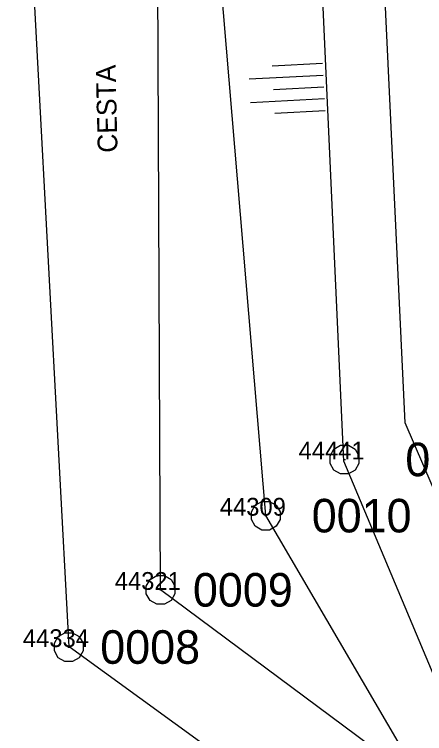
# Model space of a CAD drawing. Extents: x -598521 to -597689, y -1074676 to -1074150.
# Drawn here: x -598496.3 to -598485.91, y -1074215.4 to -1074197.17 of the extents above; entities that cross this region are included whole.
import ezdxf

# ---------------------------------------------------------------- set-up
doc = ezdxf.new("R2010")
doc.units = 0
for name, color, linetype in [('Vrstva 1', 7, 'Continuous'), ('Vrstva 10', 7, 'Continuous'), ('Vrstva 2', 7, 'Continuous'), ('Vrstva 3', 7, 'Continuous'), ('Vrstva 5', 7, 'Continuous')]:
    doc.layers.add(name, color=color, linetype=linetype)

msp = doc.modelspace()

# ---------------------------------------------------------------- linework, layer by layer
at = {"layer": 'Vrstva 1'}
for p, q in [((-598487.964, -1074208.45), (-598487.914, -1074208.45)), ((-598489.96, -1074209.873), (-598489.91, -1074209.873)), ((-598492.622, -1074211.753), (-598492.572, -1074211.753)), ((-598494.95, -1074213.202), (-598494.9, -1074213.202))]:
    msp.add_line(p, q, dxfattribs=at)
for points in [[(-598487.844, -1074208.09), (-598487.674, -1074208.185), (-598487.579, -1074208.355), (-598487.579, -1074208.55), (-598487.674, -1074208.72), (-598487.844, -1074208.815), (-598488.039, -1074208.815), (-598488.209, -1074208.72), (-598488.304, -1074208.55), (-598488.304, -1074208.355), (-598488.209, -1074208.185), (-598488.039, -1074208.09)], [(-598489.84, -1074209.513), (-598489.67, -1074209.608), (-598489.575, -1074209.778), (-598489.575, -1074209.973), (-598489.67, -1074210.143), (-598489.84, -1074210.238), (-598490.035, -1074210.238), (-598490.205, -1074210.143), (-598490.3, -1074209.973), (-598490.3, -1074209.778), (-598490.205, -1074209.608), (-598490.035, -1074209.513)], [(-598492.502, -1074211.393), (-598492.332, -1074211.488), (-598492.237, -1074211.658), (-598492.237, -1074211.853), (-598492.332, -1074212.023), (-598492.502, -1074212.118), (-598492.697, -1074212.118), (-598492.867, -1074212.023), (-598492.962, -1074211.853), (-598492.962, -1074211.658), (-598492.867, -1074211.488), (-598492.697, -1074211.393)], [(-598494.83, -1074212.842), (-598494.66, -1074212.937), (-598494.565, -1074213.107), (-598494.565, -1074213.302), (-598494.66, -1074213.472), (-598494.83, -1074213.567), (-598495.025, -1074213.567), (-598495.195, -1074213.472), (-598495.29, -1074213.302), (-598495.29, -1074213.107), (-598495.195, -1074212.937), (-598495.025, -1074212.842)]]:
    msp.add_lwpolyline(points, close=True, dxfattribs=at)
at = {"layer": 'Vrstva 10'}
for p, q in [((-598488.496, -1074198.42), (-598489.77, -1074198.488)), ((-598488.48, -1074198.719), (-598490.353, -1074198.819)), ((-598488.464, -1074199.019), (-598489.738, -1074199.087)), ((-598488.448, -1074199.318), (-598490.321, -1074199.419)), ((-598488.432, -1074199.618), (-598489.706, -1074199.686))]:
    msp.add_line(p, q, dxfattribs=at)
for points in [[(-598484.92, -1074215.734), (-598487.958, -1074208.491), (-598488.57, -1074195.13), (-598485.971, -1074186.446), (-598483.586, -1074182.241), (-598482.242, -1074177.742), (-598479.451, -1074171.782), (-598475.091, -1074167.2), (-598468.639, -1074162.188), (-598465.635, -1074160.81), (-598454.605, -1074159.518), (-598444.717, -1074161.464), (-598440.447, -1074163.564)], [(-598491.251, -1074170.54), (-598490.39, -1074175.72), (-598490.72, -1074179.9), (-598491.56, -1074186.02), (-598491.51, -1074191.2), (-598489.94, -1074209.87), (-598485.95, -1074216.7)], [(-598483.025, -1074221.641), (-598485.95, -1074216.7), (-598492.6, -1074211.75), (-598492.675, -1074194.409), (-598492.11, -1074185.98), (-598491.774, -1074180.11), (-598492.357, -1074176.088), (-598493.045, -1074170.76)], [(-598485.692, -1074225.103), (-598487.847, -1074218.331), (-598494.92, -1074213.2), (-598495.961, -1074193.667), (-598495.219, -1074186.141), (-598494.954, -1074180.929), (-598495.873, -1074176.106), (-598499.01, -1074172.05)]]:
    msp.add_lwpolyline(points, dxfattribs=at)
at = {"layer": 'Vrstva 5'}
msp.add_lwpolyline([(-598482.963, -1074215.515), (-598486.401, -1074207.525), (-598486.999, -1074195.022), (-598480.548, -1074179.991), (-598475.294, -1074170.015), (-598468.112, -1074164.562), (-598464.254, -1074162.567), (-598455.078, -1074161.455), (-598445.366, -1074162.766), (-598432.996, -1074169.084), (-598417.866, -1074175.801), (-598412.373, -1074178.959)], dxfattribs=at)

# ---------------------------------------------------------------- texts
at = {"layer": 'Vrstva 10'}
msp.add_text('CESTA', height=0.5, rotation=91.3666, dxfattribs=at).set_placement((-598493.69, -1074200.674))
at = {"layer": 'Vrstva 2'}
for s, p in [('0011', (-598486.4, -1074208.875)), ('0010', (-598488.771, -1074210.298)), ('0009', (-598491.781, -1074212.178)), ('0008', (-598494.129, -1074213.627))]:
    msp.add_text(s, height=0.85, dxfattribs=at).set_placement(p)
at = {"layer": 'Vrstva 3'}
for s, p in [('44441', (-598489.104, -1074208.45)), ('44309', (-598491.1, -1074209.873)), ('44321', (-598493.761, -1074211.753)), ('44334', (-598496.089, -1074213.202))]:
    msp.add_text(s, height=0.45, dxfattribs=at).set_placement(p)

doc.saveas('drawing.dxf')
